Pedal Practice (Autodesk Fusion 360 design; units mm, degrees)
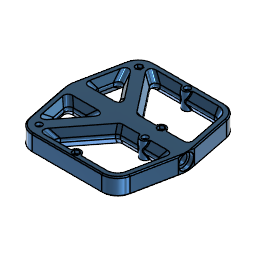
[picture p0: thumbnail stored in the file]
part number: 2025-12-16-15-12-29-748
sketch "Sketch1" plane through (0, 0, 0) normal (0, 0, 1) x axis (1, 0, 0)
  line L1 (55, -7.5) -> (-55, -7.5)
  line L2 (55, 7.5) -> (55, -7.5)
  line L3 (-55, 7.5) -> (55, 7.5)
  line L4 (-55, -7.5) -> (-55, 7.5)
  line L5 (55, 7.5) -> (-55, -7.5)
  line L6 (-55, 7.5) -> (55, -7.5)
  line L7 (55, 0) -> (-55, 0)
  line L8 (45, 57.5) -> (-45, 57.5)
  line L9 (-45, 57.5) -> (-55, 7.5)
  line L10 (55, 7.5) -> (45, 57.5)
  line L11 (-45, -57.5) -> (-55, -7.5)
  line L12 (45, -57.5) -> (-45, -57.5)
  line L13 (55, -7.5) -> (45, -57.5)
  point P6 (0, 0)
  point P1 (0, 0)
  point P7 (-55, 0)
  point P8 (55, 0)
  point P4 (55, 7.5)
  point P14 (55, -7.5)
  point P5 (-55, 7.5)
  point P11 (-55, -7.5)
  point P9 (-45, 57.5)
  point P12 (-45, -57.5)
  point P10 (45, 57.5)
  point P13 (45, -57.5)
  point P3 (55, -7.5)
  horizontal L1
  perpendicular L1 L2
  parallel L1 L3
  parallel L2 L4
  coincident L5 P6
  coincident L6 P6
  coincident P1 P6
  midpoint L4 P7
  midpoint L2 P8
  horizontal L8
  equal L9 L10
  symmetric P4 L7 P14
  symmetric P5 L7 P11
  symmetric L7 P9 P12
  symmetric L7 P10 P13
  dimension "d1" distance P4 P5 = 110
  dimension "d2" distance P3 P4 = 15
  dimension "d3" distance L7 L8 = 57.5
  dimension "d4" distance P9 P10 = 90
extrude "Extrude1" new body sketch "Sketch1" profile of L2 L4 L8 L9 L10 L11 L12 L13 distance 16
fillet "Fillet1" radius 15
sketch "Sketch2" plane through (0, 0, 8) normal (0, 0, 1) x axis (-1, 0, 0)
  line L1 (-55, 7.5) -> (-47.4117, 45.4417)
  line L2 (-55, -7.5) -> (-55, 7.5)
  line L3 (-47.4117, -45.4417) -> (-55, -7.5)
  line L4 (32.7029, -57.5) -> (-32.7029, -57.5)
  line L5 (55, -7.5) -> (47.4117, -45.4417)
  line L6 (55, 7.5) -> (55, -7.5)
  line L7 (47.4117, 45.4417) -> (55, 7.5)
  line L8 (-32.7029, 57.5) -> (32.7029, 57.5)
  line L9 (-55, -7.5) -> (55, -7.5)
  line L10 (-55, 7.5) -> (55, 7.5)
  line L11 (42.2128, -54.1001) -> (0, 0)
  line L12 (42.2128, 54.1001) -> (0, 0)
  line L13 (45.5479, 50.2465) -> (6.342, 0)
  line L14 (45.5479, -50.2465) -> (6.342, 0)
  line L15 (37.8212, 56.5998) -> (-6.342, 0)
  line L16 (37.8212, -56.5998) -> (-6.342, 0)
  line L17 (50, -7.0049) -> (42.5087, -44.4612)
  line L18 (50, 7.0049) -> (50, -7.0049)
  line L19 (42.5087, 44.4612) -> (50, 7.0049)
  line L20 (-32.7029, 52.5) -> (32.7029, 52.5)
  line L21 (-50, 7.0049) -> (-42.5087, 44.4612)
  line L22 (-50, -7.0049) -> (-50, 7.0049)
  line L23 (-42.5087, -44.4612) -> (-50, -7.0049)
  line L24 (32.7029, -52.5) -> (-32.7029, -52.5)
  arc A1 centre (-32.7029, 42.5) radius 15 clockwise from (-47.4117, 45.4417) to (-32.7029, 57.5)
  arc A2 centre (-32.7029, -42.5) radius 15 clockwise from (-32.7029, -57.5) to (-47.4117, -45.4417)
  arc A3 centre (32.7029, -42.5) radius 15 clockwise from (47.4117, -45.4417) to (32.7029, -57.5)
  arc A4 centre (32.7029, 42.5) radius 15 clockwise from (32.7029, 57.5) to (47.4117, 45.4417)
  arc A5 centre (32.7029, -42.5) radius 10 clockwise from (42.5087, -44.4612) to (32.7029, -52.5)
  arc A6 centre (32.7029, 42.5) radius 10 clockwise from (32.7029, 52.5) to (42.5087, 44.4612)
  arc A7 centre (-32.7029, 42.5) radius 10 clockwise from (-42.5087, 44.4612) to (-32.7029, 52.5)
  arc A8 centre (-32.7029, -42.5) radius 10 clockwise from (-32.7029, -52.5) to (-42.5087, -44.4612)
  point P13 (55, -7.5)
  point P18 (55, -7.5)
  point P6 (-55, -7.5)
  point P19 (-55, -7.5)
  point P14 (55, 7.5)
  point P20 (55, 7.5)
  point P5 (-55, 7.5)
  point P21 (-55, 7.5)
  point P1 (0, 0)
  point P22 (0, 0)
  point P23 (42.2128, -54.1001)
  point P24 (0, 0)
  point P25 (42.2128, 54.1001)
  point P31 (37.8212, -56.5998)
  point P28 (45.5479, -50.2465)
  point P27 (45.5479, 50.2465)
  point P30 (37.8212, 56.5998)
  coincident P13 P18
  coincident P6 P19
  coincident P14 P20
  coincident P5 P21
  coincident P1 P22
  midpoint A3 P23
  coincident P1 P24
  midpoint A4 P25
  coincident A3 P31
  coincident A3 P28
  coincident A4 P27
  coincident A4 P30
  dimension "d9" = 5
  dimension "d10" = -5 (= "-d9")
  dimension "d11" = -5
extrude "Extrude2" cut sketch "Sketch2" profile of L9 L10 L13 L14 L15 L16 A6 A5 L17 L19 L20 A7 L21 L23 A8 L24 against normal blind 8 taper -30
fillet "Fillet2" radius 5
mirror "Mirror1" mirrorStitchTolerance 0.1
fillet "Fillet3" ChordLen 3.5
sketch "Sketch3" plane through (0, 0, 0) normal (0, 0, 1) x axis (1, 0, 0)
  line L1 (55, -7.5) -> (55, 7.5)
  line L2 (55, 7.5) -> (55, -7.5)
  line L3 (-55, 7.5) -> (-55, -7.5)
  line L4 (-55, 0) -> (55, 0)
  line L5 (51, 7) -> (55, 7)
  line L6 (51, 4.5) -> (51, 7)
  line L7 (-42.5, 4.5) -> (51, 4.5)
  line L8 (-42.5, 5) -> (-42.5, 4.5)
  line L9 (-45, 5) -> (-42.5, 5)
  line L10 (-45, 7) -> (-45, 5)
  line L11 (-55, 7) -> (-45, 7)
  point P6 (55, 0)
  point P7 (-55, 0)
  point P8 (55, 7)
  point P15 (-55, 7)
  point P9 (51, 7)
  point P10 (51, 4.5)
  point P11 (-42.5, 4.5)
  point P12 (-42.5, 5)
  midpoint L2 P6
  midpoint L3 P7
  coincident L1 P8
  perpendicular L1 L5
  perpendicular L5 L6
  perpendicular L6 L7
  perpendicular L7 L8
  perpendicular L3 L9
  perpendicular L9 L10
  coincident L3 P15
  perpendicular L3 L11
  dimension "d20" = 14
  dimension "d21" distance P8 P9 = 4
  dimension "d22" = 9
  dimension "d23" distance P10 P11 = 93.5
  dimension "d24" = 10
  dimension "d25" distance P12 L10 = 2.5
  dimension "d26" = 14
revolve "Revolve1" sketch "Sketch3" AlongAngle 360
sketch "Screw Loc" plane through (0, 0, 8) normal (0, 0, 1) x axis (-1, 0, 0)
  line L1 (44.0595, -36.7075) -> (48.8651, -12.6793)
  line L2 (17.6511, -14.4939) -> (36.3996, -38.522)
  line L3 (44.6191, -7.5) -> (21.065, -7.5)
  line L4 (-48.8651, -12.6793) -> (-42.5087, -44.4612)
  line L5 (-2.6036, -7.5) -> (-44.6191, -7.5)
  line L6 (29.1652, -45.5061) -> (0.8103, -9.1664)
  line L7 (-32.7029, -52.5) -> (25.7513, -52.5)
  line L8 (48.8651, 12.6793) -> (44.0595, 36.7075)
  line L9 (21.065, 7.5) -> (44.6191, 7.5)
  line L10 (36.3996, 38.522) -> (17.6511, 14.4939)
  line L11 (0.8103, 9.1664) -> (29.1652, 45.5061)
  line L12 (-44.6191, 7.5) -> (-2.6036, 7.5)
  line L13 (-42.5087, 44.4612) -> (-48.8651, 12.6793)
  line L14 (25.7513, 52.5) -> (-32.7029, 52.5)
  line L15 (-55, 7.5) -> (-47.4117, 45.4417)
  line L16 (-55, -7.5) -> (-55, 7.5)
  line L17 (-47.4117, -45.4417) -> (-55, -7.5)
  line L18 (32.7029, -57.5) -> (-32.7029, -57.5)
  line L19 (55, -7.5) -> (47.4117, -45.4417)
  line L20 (55, 7.5) -> (55, -7.5)
  line L21 (47.4117, 45.4417) -> (55, 7.5)
  line L22 (-32.7029, 57.5) -> (32.7029, 57.5)
  line L23 (42.2128, -54.1001) -> (0, 0)
  line L24 (55, 0) -> (0, 0)
  closed curve K1 centre (39.0153, -32.4891)
  closed curve K2 centre (24.022, -13.2735)
  closed curve K3 centre (42.8584, -13.2735)
  closed curve K4 centre (-42.8584, -13.2735)
  closed curve K5 centre (-3.3081, -13.2735)
  closed curve K6 centre (22.7943, -46.7265)
  arc A1 centre (-32.7029, -42.5) radius 10 clockwise from (-32.7029, -52.5) to (-42.5087, -44.4612)
  closed curve K7 centre (42.8584, 13.2735)
  closed curve K8 centre (24.022, 13.2735)
  closed curve K9 centre (39.0153, 32.4891)
  closed curve K10 centre (22.7943, 46.7265)
  closed curve K11 centre (-3.3081, 13.2735)
  closed curve K12 centre (-42.8584, 13.2735)
  arc A2 centre (-32.7029, 42.5) radius 10 clockwise from (-42.5087, 44.4612) to (-32.7029, 52.5)
  arc A3 centre (-32.7029, 42.5) radius 15 clockwise from (-47.4117, 45.4417) to (-32.7029, 57.5)
  arc A4 centre (-32.7029, -42.5) radius 15 clockwise from (-32.7029, -57.5) to (-47.4117, -45.4417)
  arc A5 centre (32.7029, -42.5) radius 15 clockwise from (47.4117, -45.4417) to (32.7029, -57.5)
  arc A6 centre (32.7029, 42.5) radius 15 clockwise from (32.7029, 57.5) to (47.4117, 45.4417)
  circle C1 centre (-3.4758, -52.5) radius 4.5
  circle C2 centre (36.6763, -47.0045) radius 4.5
  circle C3 centre (-23.6113, -7.5) radius 4.5
  circle C4 centre (-23.6113, -7.5) radius 2.75
  circle C5 centre (-3.4758, -52.5) radius 2.75
  circle C6 centre (36.6763, -47.0045) radius 2.75
  circle C7 centre (36.6763, 47.0045) radius 4.5
  circle C8 centre (36.6763, 47.0045) radius 2.75
  circle C9 centre (-3.4758, 52.5) radius 4.5
  circle C10 centre (-3.4758, 52.5) radius 2.75
  circle C11 centre (-23.6113, 7.5) radius 4.5
  circle C12 centre (-23.6113, 7.5) radius 2.75
  point P58 (-3.4758, -52.5)
  point P61 (36.6763, -47.0045)
  point P59 (0, 0)
  point P62 (0, 0)
  point P63 (55, 0)
  point P64 (-23.6113, -7.5)
  point P60 (42.2128, -54.1001)
  midpoint L7 P58
  coincident L23 P61
  coincident P59 P62
  midpoint L20 P63
  coincident L5 P64
  midpoint L5 P64
  equal C1 C3
  concentric C3 C4
  concentric C1 C5
  concentric C2 C6
  equal C5 C6
  equal C4 C5
  symmetric C1 L24 C9
  symmetric C2 L24 C7
  symmetric L24 C3 C11
  symmetric L24 C4 C12
  symmetric L24 C5 C10
  symmetric L24 C6 C8
  dimension "d28" diameter C1 = 9
  dimension "d29" diameter C2 = 9
  dimension "d30" distance P60 P61 = 9
  dimension "d31" diameter C4 = 5.5
extrude "Extrude3" add sketch "Screw Loc" profile of L5 L7 L12 L14 C1 C3 C4 C5 C9 C10 C11 C12 to an object
extrude "Extrude4" cut sketch "Screw Loc" profile of L7 L12 C5 C8 C12 against normal blind 3
extrude "Extrude5" sketch "Screw Loc" profile of L5 L14 C4 C6 C10 blind 3
sketch "Sketch5" plane through (0, 0, 8) normal (0, 0, 1) x axis (-1, 0, 0)
  line L1 (44.0595, -36.7075) -> (48.8651, -12.6793)
  line L2 (17.6511, -14.4939) -> (36.3996, -38.522)
  line L3 (44.6191, -7.5) -> (21.065, -7.5)
  line L4 (-48.8651, -12.6793) -> (-42.5087, -44.4612)
  line L5 (-28.1113, -7.5) -> (-44.6191, -7.5)
  line L6 (-2.6036, -7.5) -> (-19.1113, -7.5)
  line L7 (29.1652, -45.5061) -> (0.8103, -9.1664)
  line L8 (1.0242, -52.5) -> (25.7513, -52.5)
  line L9 (-32.7029, -52.5) -> (-7.9758, -52.5)
  line L10 (48.8651, 12.6793) -> (44.0595, 36.7075)
  line L11 (21.065, 7.5) -> (44.6191, 7.5)
  line L12 (36.3996, 38.522) -> (17.6511, 14.4939)
  line L13 (0.8103, 9.1664) -> (29.1652, 45.5061)
  line L14 (-19.1113, 7.5) -> (-2.6036, 7.5)
  line L15 (-44.6191, 7.5) -> (-28.1113, 7.5)
  line L16 (-42.5087, 44.4612) -> (-48.8651, 12.6793)
  line L17 (-7.9758, 52.5) -> (-32.7029, 52.5)
  line L18 (25.7513, 52.5) -> (1.0242, 52.5)
  line L19 (-55, 7.5) -> (-47.4117, 45.4417)
  line L20 (-55, -7.5) -> (-55, 7.5)
  line L21 (-47.4117, -45.4417) -> (-55, -7.5)
  line L22 (32.7029, -57.5) -> (-32.7029, -57.5)
  line L23 (55, -7.5) -> (47.4117, -45.4417)
  line L24 (55, 7.5) -> (55, -7.5)
  line L25 (47.4117, 45.4417) -> (55, 7.5)
  line L26 (-32.7029, 57.5) -> (32.7029, 57.5)
  line L27 (-0.6008, -54.1599) -> (-3.4758, -55.8198)
  line L28 (-0.6008, -50.8401) -> (-0.6008, -54.1599)
  line L29 (-3.4758, -49.1802) -> (-0.6008, -50.8401)
  line L30 (-6.3508, -50.8401) -> (-3.4758, -49.1802)
  line L31 (-6.3508, -54.1599) -> (-6.3508, -50.8401)
  line L32 (-3.4758, -55.8198) -> (-6.3508, -54.1599)
  line L33 (39.5513, -48.6644) -> (36.6763, -50.3243)
  line L34 (39.5513, -45.3447) -> (39.5513, -48.6644)
  line L35 (36.6763, -43.6848) -> (39.5513, -45.3447)
  line L36 (33.8013, -45.3447) -> (36.6763, -43.6848)
  line L37 (33.8013, -48.6644) -> (33.8013, -45.3447)
  line L38 (36.6763, -50.3243) -> (33.8013, -48.6644)
  line L39 (-23.6113, -10.8198) -> (-26.4863, -9.1599)
  line L40 (-20.7363, -9.1599) -> (-23.6113, -10.8198)
  line L41 (-20.7363, -5.8401) -> (-20.7363, -9.1599)
  line L42 (-23.6113, -4.1802) -> (-20.7363, -5.8401)
  line L43 (-26.4863, -5.8401) -> (-23.6113, -4.1802)
  line L44 (-26.4863, -9.1599) -> (-26.4863, -5.8401)
  line L45 (-20.7363, 5.8401) -> (-23.6113, 4.1802)
  line L46 (-20.7363, 9.1599) -> (-20.7363, 5.8401)
  line L47 (-23.6113, 10.8198) -> (-20.7363, 9.1599)
  line L48 (-26.4863, 9.1599) -> (-23.6113, 10.8198)
  line L49 (-26.4863, 5.8401) -> (-26.4863, 9.1599)
  line L50 (-23.6113, 4.1802) -> (-26.4863, 5.8401)
  line L51 (-0.6008, 50.8401) -> (-3.4758, 49.1802)
  line L52 (-0.6008, 54.1599) -> (-0.6008, 50.8401)
  line L53 (-3.4758, 55.8198) -> (-0.6008, 54.1599)
  line L54 (-6.3508, 54.1599) -> (-3.4758, 55.8198)
  line L55 (-6.3508, 50.8401) -> (-6.3508, 54.1599)
  line L56 (-3.4758, 49.1802) -> (-6.3508, 50.8401)
  line L57 (39.5513, 45.3447) -> (36.6763, 43.6848)
  line L58 (39.5513, 48.6644) -> (39.5513, 45.3447)
  line L59 (36.6763, 50.3243) -> (39.5513, 48.6644)
  line L60 (33.8013, 48.6644) -> (36.6763, 50.3243)
  line L61 (33.8013, 45.3447) -> (33.8013, 48.6644)
  line L62 (36.6763, 43.6848) -> (33.8013, 45.3447)
  circle C1 centre (36.6763, 47.0045) radius 2.75
  circle C2 centre (-23.6113, 7.5) radius 2.75
  circle C3 centre (-3.4758, -52.5) radius 2.75
  closed curve K1 centre (39.0153, -32.4891)
  closed curve K2 centre (24.022, -13.2735)
  closed curve K3 centre (42.8584, -13.2735)
  closed curve K4 centre (-42.8584, -13.2735)
  arc A1 centre (-23.6113, -7.5) radius 4.5 clockwise from (-19.1113, -7.5) to (-28.1113, -7.5)
  closed curve K5 centre (-3.3081, -13.2735)
  closed curve K6 centre (22.7943, -46.7265)
  arc A2 centre (-3.4758, -52.5) radius 4.5 clockwise from (-7.9758, -52.5) to (1.0242, -52.5)
  arc A3 centre (-32.7029, -42.5) radius 10 clockwise from (-32.7029, -52.5) to (-42.5087, -44.4612)
  closed curve K7 centre (42.8584, 13.2735)
  closed curve K8 centre (24.022, 13.2735)
  closed curve K9 centre (39.0153, 32.4891)
  closed curve K10 centre (22.7943, 46.7265)
  closed curve K11 centre (-3.3081, 13.2735)
  arc A4 centre (-23.6113, 7.5) radius 4.5 clockwise from (-28.1113, 7.5) to (-19.1113, 7.5)
  closed curve K12 centre (-42.8584, 13.2735)
  arc A5 centre (-32.7029, 42.5) radius 10 clockwise from (-42.5087, 44.4612) to (-32.7029, 52.5)
  arc A6 centre (-3.4758, 52.5) radius 4.5 clockwise from (1.0242, 52.5) to (-7.9758, 52.5)
  arc A7 centre (-32.7029, 42.5) radius 15 clockwise from (-47.4117, 45.4417) to (-32.7029, 57.5)
  arc A8 centre (-32.7029, -42.5) radius 15 clockwise from (-32.7029, -57.5) to (-47.4117, -45.4417)
  arc A9 centre (32.7029, -42.5) radius 15 clockwise from (47.4117, -45.4417) to (32.7029, -57.5)
  arc A10 centre (32.7029, 42.5) radius 15 clockwise from (32.7029, 57.5) to (47.4117, 45.4417)
  point P72 (-3.4758, -52.5)
  point P83 (-3.4758, -52.5)
  point P71 (36.6763, -47.0045)
  point P90 (36.6763, -47.0045)
  point P20 (-23.6113, -7.5)
  point P97 (-23.6113, -7.5)
  point P3 (-23.6113, 7.5)
  point P104 (-23.6113, 7.5)
  point P75 (-3.4758, 52.5)
  point P111 (-3.4758, 52.5)
  point P76 (36.6763, 47.0045)
  point P118 (36.6763, 47.0045)
  coincident P72 P83
  vertical L28
  coincident P71 P90
  coincident P20 P97
  coincident P3 P104
  coincident P75 P111
  coincident P76 P118
  vertical L61
  vertical L52
  vertical L46
  vertical L44
  vertical L37
  equal L31 L37
  equal L31 L44
  equal L44 L49
  equal L49 L55
  equal L55 L61
  dimension "d39" distance L28 L31 = 5.75
extrude "Extrude6" cut sketch "Sketch5" profile of L33 L34 L35 L36 L37 L38 L39 L40 L41 L42 L43 L44 L51 L52 L53 L54 L55 L56 against normal blind 3
extrude "Extrude7" sketch "Sketch5" profile of C1 C2 C3 L27 L28 L29 L30 L31 L32 L45 L46 L47 L48 L49 L50 L57 L58 L59 L60 L61 L62 blind 3
hole "Hole1" HoleDiameter 3 TipAngle 180
fillet "Fillet4" ChordLen 1
chamfer "Chamfer1" distance 1
chamfer "Chamfer2" distance 0.25
thread "Thread1" ThreadOffset 0 ThreadLength 10
chamfer "Chamfer3" distance 0.25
